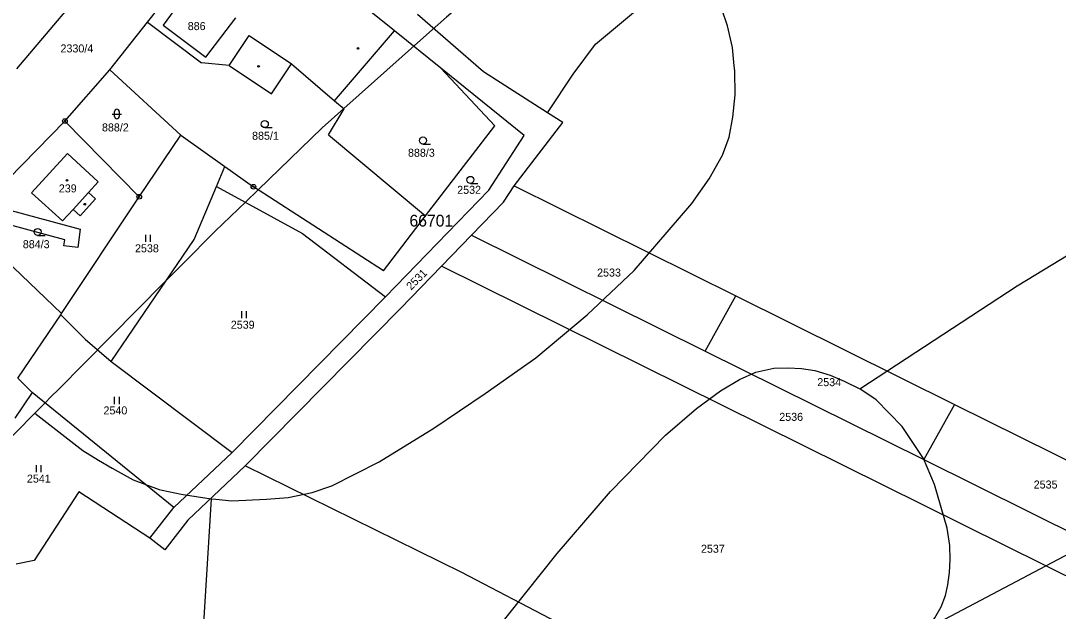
# Model space of a CAD drawing. Extents: x -546762 to -540209, y -1046851 to -1035694.
# Drawn here: x -542845.1 to -542624.6, y -1040164.6 to -1040039.2 of the extents above; entities that cross this region are included whole.
import ezdxf

# ---------------------------------------------------------------- set-up
doc = ezdxf.new("R2010")
doc.units = 0
for name, color, linetype in [('Vrstva 1', 7, 'Continuous'), ('Vrstva 16', 7, 'Continuous'), ('Vrstva 18', 7, 'Continuous'), ('Vrstva 19', 7, 'Continuous'), ('Vrstva 24', 7, 'Continuous'), ('Vrstva 25', 7, 'Continuous'), ('Vrstva 3', 7, 'Continuous'), ('Vrstva 30', 7, 'Continuous'), ('Vrstva 37', 7, 'Continuous'), ('Vrstva 4', 7, 'Continuous'), ('Vrstva 52', 7, 'Continuous'), ('Vrstva 53', 7, 'Continuous')]:
    doc.layers.add(name, color=color, linetype=linetype)

msp = doc.modelspace()

# ---------------------------------------------------------------- linework, layer by layer
at = {"layer": 'Vrstva 1'}
for p, q in [((-542778.4, -1040056.18), (-542765.64, -1040041.36)), ((-542826.16, -1040049.64), (-542811.06, -1040063.5)), ((-542835.71, -1040060.51), (-542819.91, -1040076.58)), ((-542779.71, -1040063.45), (-542759.07, -1040080.67)), ((-542836.4, -1040101.36), (-542856.77, -1040081.96))]:
    msp.add_line(p, q, dxfattribs=at)
for points in [[(-542818.13, -1040039.5), (-542797.08, -1040012.91)], [(-542827.49, -1040027.57), (-542845.99, -1040049.42)], [(-542809.19, -1040032.37), (-542814.84, -1040040.17)], [(-542722.99, -1040044.16), (-542712.77, -1040035.71)], [(-542765.64, -1040041.36), (-542771.43, -1040036.71)], [(-542746.73, -1040050.07), (-542760.8, -1040037.84)], [(-542826.16, -1040049.64), (-542818.13, -1040039.5)], [(-542818.13, -1040039.5), (-542806.66, -1040048.11)], [(-542814.84, -1040040.17), (-542805.78, -1040046.95)], [(-542805.78, -1040046.95), (-542799.37, -1040038.59)], [(-542755.84, -1040049.24), (-542765.64, -1040041.36)], [(-542727.71, -1040050.58), (-542722.99, -1040044.16)], [(-542800.79, -1040048.71), (-542806.66, -1040048.11)], [(-542800.79, -1040048.71), (-542791.81, -1040054.72)], [(-542791.81, -1040054.72), (-542787.55, -1040048.36)], [(-542787.55, -1040048.36), (-542778.4, -1040056.18)], [(-542835.71, -1040060.51), (-542826.16, -1040049.64)], [(-542738.14, -1040063.58), (-542755.84, -1040049.24)], [(-542755.84, -1040049.24), (-542744.37, -1040061.54)], [(-542733.17, -1040058.73), (-542746.73, -1040050.07)], [(-542733.17, -1040058.73), (-542727.71, -1040050.58)], [(-542778.4, -1040056.18), (-542776.34, -1040057.94)], [(-542779.71, -1040063.45), (-542776.34, -1040057.94)], [(-542729.9, -1040060.82), (-542733.17, -1040058.73)], [(-542856.77, -1040081.96), (-542835.71, -1040060.51)], [(-542759.07, -1040080.67), (-542744.37, -1040061.54)], [(-542740.28, -1040074.27), (-542729.9, -1040060.82)], [(-542819.91, -1040076.58), (-542811.06, -1040063.5)], [(-542811.06, -1040063.5), (-542801.7, -1040070.15)], [(-542745.64, -1040075.21), (-542738.14, -1040063.58)], [(-542835.17, -1040067.39), (-542842.78, -1040075.74)], [(-542828.61, -1040073.42), (-542835.17, -1040067.39)], [(-542803.49, -1040074.38), (-542801.7, -1040070.15)], [(-542801.7, -1040070.15), (-542795.64, -1040074.45)], [(-542830.71, -1040075.7), (-542828.61, -1040073.42)], [(-542808.23, -1040085.63), (-542803.49, -1040074.38)], [(-542803.49, -1040074.38), (-542785.23, -1040084.38)], [(-542768.02, -1040092.31), (-542795.64, -1040074.45)], [(-542767.57, -1040097.83), (-542745.64, -1040075.21)], [(-542742.5, -1040077.71), (-542740.28, -1040074.27)], [(-542740.28, -1040074.27), (-542693.15, -1040097.64)], [(-542842.78, -1040075.74), (-542836.2, -1040081.69)], [(-542836.4, -1040101.36), (-542819.91, -1040076.58)], [(-542832.49, -1040080.61), (-542829.23, -1040077.06)], [(-542829.23, -1040077.06), (-542830.71, -1040075.7)], [(-542836.2, -1040081.69), (-542833.97, -1040079.26)], [(-542833.97, -1040079.26), (-542832.49, -1040080.61)], [(-542749.33, -1040084.75), (-542742.5, -1040077.71)], [(-542768.02, -1040092.31), (-542759.07, -1040080.67)], [(-542825.88, -1040111.55), (-542808.23, -1040085.63)], [(-542785.23, -1040084.38), (-542767.57, -1040097.83)], [(-542755.68, -1040091.32), (-542749.33, -1040084.75)], [(-542749.33, -1040084.75), (-542699.66, -1040109.38)], [(-542764.35, -1040100.27), (-542755.68, -1040091.32)], [(-542610.45, -1040163.32), (-542755.68, -1040091.32)], [(-542767.57, -1040097.83), (-542800.19, -1040130.87)], [(-542699.66, -1040109.38), (-542693.15, -1040097.64)], [(-542693.15, -1040097.64), (-542646.67, -1040120.68)], [(-542845.68, -1040115.08), (-542836.58, -1040101.63)], [(-542836.58, -1040101.63), (-542836.4, -1040101.36)], [(-542836.58, -1040101.63), (-542831.37, -1040106.85)], [(-542797.39, -1040133.73), (-542764.35, -1040100.27)], [(-542831.37, -1040106.85), (-542825.88, -1040111.55)], [(-542699.66, -1040109.38), (-542653.18, -1040132.42)], [(-542825.88, -1040111.55), (-542800.19, -1040130.87)], [(-542845.68, -1040115.08), (-542842.64, -1040118.15)], [(-542842.64, -1040118.15), (-542846.35, -1040123.64)], [(-542812.55, -1040142.57), (-542842.64, -1040118.15)], [(-542646.67, -1040120.68), (-542653.18, -1040132.42)], [(-542646.67, -1040120.68), (-542604.65, -1040141.51)], [(-542800.19, -1040130.87), (-542812.55, -1040142.57)], [(-542653.18, -1040132.42), (-542608.17, -1040154.73)], [(-542797.39, -1040133.73), (-542809.58, -1040145.26)], [(-542751.35, -1040156.39), (-542797.39, -1040133.73)], [(-542832.72, -1040139.28), (-542842.25, -1040153.87)], [(-542817.63, -1040149.11), (-542832.72, -1040139.28)], [(-542817.63, -1040149.11), (-542812.55, -1040142.57)], [(-542809.58, -1040145.26), (-542814.47, -1040151.56)], [(-542814.47, -1040151.56), (-542817.63, -1040149.11)], [(-542842.25, -1040153.87), (-542846.06, -1040154.63)], [(-542731.05, -1040167), (-542751.35, -1040156.39)]]:
    msp.add_lwpolyline(points, dxfattribs=at)
at = {"layer": 'Vrstva 24'}
for centre, radius in [((-542835.71, -1040060.51), 0.5), ((-542835.71, -1040060.51), 0.1), ((-542795.64, -1040074.45), 0.5), ((-542795.64, -1040074.45), 0.1), ((-542819.91, -1040076.58), 0.5), ((-542819.91, -1040076.58), 0.1)]:
    msp.add_circle(centre, radius, dxfattribs=at)
at = {"layer": 'Vrstva 25'}
for p, q in [((-542825.66, -1040059.01), (-542823.66, -1040059.01)), ((-542825.16, -1040059.51), (-542825.16, -1040058.51)), ((-542824.16, -1040058.51), (-542824.16, -1040059.51)), ((-542793.23, -1040061.9), (-542791.63, -1040061.9)), ((-542759.62, -1040065.39), (-542758.02, -1040065.39)), ((-542749.55, -1040073.75), (-542747.95, -1040073.75)), ((-542841.49, -1040084.81), (-542839.89, -1040084.81)), ((-542818.5, -1040086.17), (-542818.5, -1040084.67)), ((-542817.5, -1040086.17), (-542817.5, -1040084.67)), ((-542798.14, -1040102.4), (-542798.14, -1040100.9)), ((-542797.14, -1040102.4), (-542797.14, -1040100.9)), ((-542825.13, -1040120.6), (-542825.13, -1040119.1)), ((-542824.13, -1040120.6), (-542824.13, -1040119.1)), ((-542841.73, -1040135.09), (-542841.73, -1040133.59)), ((-542840.73, -1040135.09), (-542840.73, -1040133.59))]:
    msp.add_line(p, q, dxfattribs=at)
for centre, radius in [((-542773.44, -1040045.08), 0.175), ((-542794.55, -1040048.87), 0.175), ((-542793.23, -1040061.15), 0.75), ((-542759.62, -1040064.64), 0.75), ((-542835.27, -1040073.09), 0.175), ((-542749.55, -1040073), 0.75), ((-542831.47, -1040078.17), 0.175), ((-542841.49, -1040084.06), 0.75)]:
    msp.add_circle(centre, radius, dxfattribs=at)
for centre, start, end in [((-542824.66, -1040058.51), 0, 180), ((-542824.66, -1040059.51), 180, 0)]:
    msp.add_arc(centre, 0.5, start, end, dxfattribs=at)
at = {"layer": 'Vrstva 3'}
for points in [[(-542835.17, -1040067.39), (-542842.78, -1040075.74)], [(-542828.61, -1040073.42), (-542835.17, -1040067.39)], [(-542830.71, -1040075.7), (-542828.61, -1040073.42)], [(-542842.78, -1040075.74), (-542836.2, -1040081.69)], [(-542833.97, -1040079.26), (-542830.71, -1040075.7)], [(-542836.2, -1040081.69), (-542833.97, -1040079.26)]]:
    msp.add_lwpolyline(points, dxfattribs=at)
at = {"layer": 'Vrstva 30'}
msp.add_lwpolyline([(-542832.43, -1040083.48), (-542832.92, -1040087.36), (-542835.9, -1040086.98), (-542835.73, -1040085.7), (-542851.7, -1040081.41), (-542854.69, -1040079.84), (-542852.49, -1040077.6), (-542850.6, -1040078.59), (-542832.43, -1040083.48)], dxfattribs=at)
at = {"layer": 'Vrstva 37'}
msp.add_circle((-542835.27, -1040073.09), 0.175, dxfattribs=at)
at = {"layer": 'Vrstva 4'}
for points in [[(-542800.79, -1040048.71), (-542796.53, -1040042.35)], [(-542796.53, -1040042.35), (-542787.55, -1040048.36)], [(-542833.97, -1040079.26), (-542830.71, -1040075.7)]]:
    msp.add_lwpolyline(points, dxfattribs=at)
at = {"layer": 'Vrstva 52'}
for points in [[(-542711.79, -1040001.59), (-542733.4, -1040020.17), (-542754.62, -1040038.42), (-542757.69, -1040041.16), (-542760.79, -1040043.92), (-542776.43, -1040057.86), (-542781.02, -1040061.95), (-542794.66, -1040075.13), (-542797.26, -1040077.64), (-542803.76, -1040083.92), (-542810.64, -1040090.85), (-542814.58, -1040094.82), (-542837.23, -1040117.64), (-542838.47, -1040118.89), (-542840.1, -1040120.54), (-542842.09, -1040122.56)], [(-542792.89, -1040140.79), (-542788.28, -1040140.45), (-542783.16, -1040139.43), (-542778.96, -1040137.96), (-542768.95, -1040132.88), (-542757.3, -1040125.7), (-542746.4, -1040118.38), (-542735.64, -1040110.76), (-542724.74, -1040101.64), (-542714.73, -1040092.23), (-542702.49, -1040078.01), (-542698.82, -1040072.8), (-542696.01, -1040067.77), (-542694.56, -1040063.92), (-542693.79, -1040059.65), (-542693.28, -1040054.96), (-542693.36, -1040049.83), (-542693.47, -1040048.81), (-542693.87, -1040044.88), (-542694.9, -1040040.27), (-542696.09, -1040036.77)], [(-542666.8, -1040117.35), (-542633.38, -1040095.5), (-542625.77, -1040090.87), (-542609.33, -1040080.86), (-542590.25, -1040070.4), (-542584.96, -1040067.51)], [(-542748.05, -1040173.6), (-542731.08, -1040152.32), (-542719.76, -1040139.17), (-542708.11, -1040127.21), (-542701.54, -1040121.53), (-542696.42, -1040117.78), (-542692.4, -1040115.39), (-542688.9, -1040113.85), (-542685.06, -1040112.99), (-542682.08, -1040112.91), (-542679.17, -1040113.08), (-542676.36, -1040113.51), (-542673.11, -1040114.45), (-542670.13, -1040115.73), (-542666.8, -1040117.35)], [(-542652.53, -1040168.27), (-542650.87, -1040166.02), (-542649.55, -1040163.68), (-542648.63, -1040161.24), (-542648.09, -1040159), (-542647.75, -1040156.41), (-542647.6, -1040153.63), (-542647.7, -1040150.65), (-542648.28, -1040146.98), (-542650.92, -1040137.67), (-542653.31, -1040132.21), (-542657.84, -1040125.38), (-542663.3, -1040119.74), (-542666.8, -1040117.35)], [(-542842.09, -1040122.56), (-542854.46, -1040135.05), (-542867.46, -1040148.18), (-542869.76, -1040150.5)], [(-542842.09, -1040122.56), (-542831.9, -1040130.46), (-542828.53, -1040132.5), (-542825.67, -1040134.22), (-542821.23, -1040136.69), (-542815.68, -1040138.74), (-542815, -1040138.89), (-542810.99, -1040139.77), (-542804.59, -1040140.71)], [(-542804.59, -1040140.71), (-542806.7, -1040174.1), (-542809.32, -1040216.73), (-542810.18, -1040234.74), (-542810.36, -1040238.5), (-542810.88, -1040249.43), (-542811.51, -1040273.94), (-542811.24, -1040297.48), (-542809.94, -1040316.31), (-542809.11, -1040321.2), (-542807.06, -1040333.31), (-542803.14, -1040351.36), (-542797.91, -1040371.76)], [(-542804.59, -1040140.71), (-542803.65, -1040140.8), (-542800.23, -1040141.14), (-542792.89, -1040140.79)], [(-542652.53, -1040168.27), (-542601.96, -1040141.62)]]:
    msp.add_lwpolyline(points, dxfattribs=at)

# ---------------------------------------------------------------- texts
at = {"layer": 'Vrstva 16'}
msp.add_text('2330/4', height=1.7, dxfattribs=at).set_placement((-542836.63, -1040045.93))
at = {"layer": 'Vrstva 18'}
for s, p in [('886', (-542809.6, -1040041.19)), ('888/2', (-542827.82, -1040062.71)), ('885/1', (-542795.93, -1040064.48)), ('888/3', (-542762.8, -1040068.09)), ('2532', (-542752.35, -1040075.96)), ('884/3', (-542844.64, -1040087.51)), ('2538', (-542820.8, -1040088.38)), ('2533', (-542722.62, -1040093.53)), ('2539', (-542800.45, -1040104.61)), ('2534', (-542675.84, -1040116.81)), ('2540', (-542827.5, -1040122.81)), ('2536', (-542683.92, -1040124.18)), ('2541', (-542843.77, -1040137.3)), ('2535', (-542629.86, -1040138.55)), ('2537', (-542700.55, -1040152.19))]:
    msp.add_text(s, height=1.7, dxfattribs=at).set_placement(p)
msp.add_text('2531', height=1.7, rotation=45.0239, dxfattribs=at).set_placement((-542762.15, -1040096.53))
at = {"layer": 'Vrstva 19'}
msp.add_text('239', height=1.7, dxfattribs=at).set_placement((-542836.99, -1040075.66))
at = {"layer": 'Vrstva 53'}
msp.add_text('66701', height=2.5, dxfattribs=at).set_placement((-542762.49, -1040082.91))

doc.saveas('drawing.dxf')
